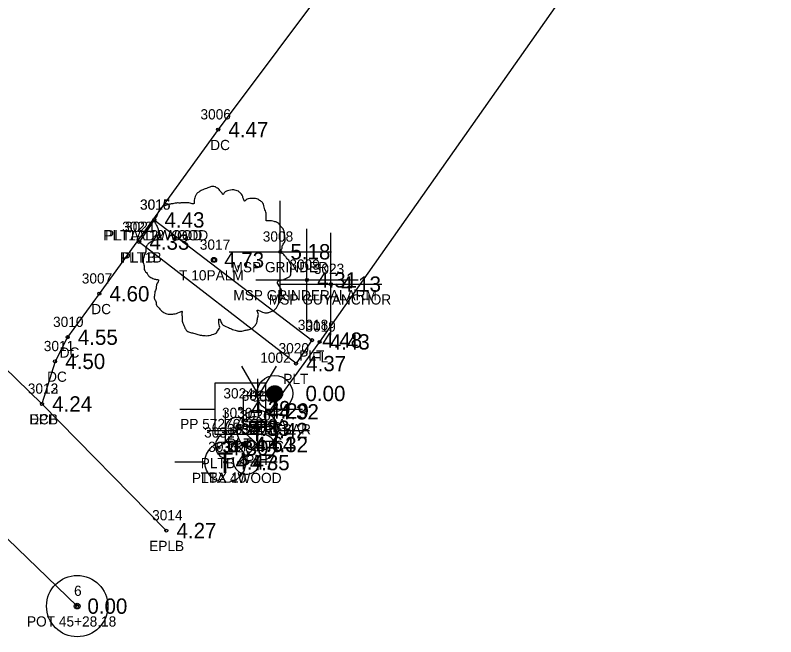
# Model space of a CAD drawing. Extents: x 2608598 to 2610682, y 641451 to 643526.
# Drawn here: x 2610257.6 to 2610332, y 641972.9 to 642033.7 of the extents above; entities that cross this region are included whole.
import ezdxf

# ---------------------------------------------------------------- set-up
doc = ezdxf.new("R2010")
doc.units = 0
for name, color, linetype in [('RD_EX_BldgApp', 7, 'Continuous'), ('RD_EX_BldgApp_txCode', 7, 'Continuous'), ('RD_EX_Conc', 7, 'Continuous'), ('RD_EX_Conc_txCode', 7, 'Continuous'), ('RD_EX_DV_Prop_txCode', 7, 'Continuous'), ('RD_EX_DV_PropPin', 7, 'Continuous'), ('RD_EX_Fence_Other', 7, 'Continuous'), ('RD_EX_Fence_Other_txCode', 7, 'Continuous'), ('RD_EX_Misc', 7, 'Continuous'), ('RD_EX_Misc_txCode', 7, 'Continuous'), ('RD_EX_Road', 7, 'Continuous'), ('RD_EX_Road_txCode', 7, 'Continuous'), ('RD_EX_TX_BldgApp_ELEV', 7, 'Continuous'), ('RD_EX_TX_Conc_ELEV', 7, 'Continuous'), ('RD_EX_TX_DV_Prop_ELEV', 7, 'Continuous'), ('RD_EX_TX_Fence_Other_ELEV', 7, 'Continuous'), ('RD_EX_TX_Misc_ELEV', 7, 'Continuous'), ('RD_EX_TX_Road_ELEV', 7, 'Continuous'), ('RD_EX_TX_UT_ELEV', 7, 'Continuous'), ('RD_EX_TX_VEG_ELEV', 7, 'Continuous'), ('RD_EX_UT', 7, 'Continuous'), ('RD_EX_UT_txCode', 7, 'Continuous'), ('RD_EX_VEG', 7, 'Continuous'), ('RD_EX_VEG_txCode', 7, 'Continuous'), ('RD_HC_Cl', 7, 'Continuous'), ('RD_HC_Data', 7, 'Continuous'), ('RD_HC_Survey_ELEV', 7, 'Continuous'), ('RD_HC_txCode', 7, 'Continuous'), ('RD_SMD_Locator', 7, 'Continuous')]:
    doc.layers.add(name, color=color, linetype=linetype)

msp = doc.modelspace()

# ---------------------------------------------------------------- linework, layer by layer
at = {"layer": 'RD_EX_BldgApp'}
msp.add_line((2610271.215, 642013.631), (2610269.738, 642011.463), dxfattribs=at)
for points in [[(2610271.215, 642013.631), (2610286.635, 642001.871), (2610285.075, 641999.583), (2610269.738, 642011.463)], [(2610279.547, 641989.897), (2610281.347, 641991.666), (2610279.543, 641993.257), (2610277.471, 641991.345)]]:
    msp.add_lwpolyline(points, dxfattribs=at)
at = {"layer": 'RD_EX_Conc'}
msp.add_lwpolyline([(2610289.126, 642038.103), (2610277.463, 642022.461), (2610265.831, 642006.412), (2610262.737, 642002.162), (2610261.507, 641999.797), (2610260.227, 641995.633)], dxfattribs=at)
at = {"layer": 'RD_EX_DV_PropPin'}
for p, q in [((2610282.336, 641996.287), (2610282.336, 641997.026)), ((2610282.371, 641996.23), (2610282.371, 641997.083)), ((2610282.406, 641996.183), (2610282.406, 641997.131)), ((2610282.441, 641996.142), (2610282.441, 641997.172)), ((2610282.476, 641996.106), (2610282.476, 641997.207)), ((2610282.511, 641996.075), (2610282.511, 641997.239)), ((2610282.546, 641996.047), (2610282.546, 641997.267)), ((2610282.582, 641996.022), (2610282.582, 641997.291)), ((2610282.617, 641996), (2610282.617, 641997.313)), ((2610282.652, 641995.981), (2610282.652, 641997.332)), ((2610282.687, 641995.964), (2610282.687, 641997.349)), ((2610282.722, 641995.949), (2610282.722, 641997.364)), ((2610282.757, 641995.936), (2610282.757, 641997.377)), ((2610282.792, 641995.925), (2610282.792, 641997.388)), ((2610282.827, 641995.916), (2610282.827, 641997.397)), ((2610282.862, 641995.909), (2610282.862, 641997.405)), ((2610282.897, 641995.903), (2610282.897, 641997.41)), ((2610282.932, 641995.899), (2610282.932, 641997.414)), ((2610282.967, 641995.896), (2610282.967, 641997.417)), ((2610283.002, 641995.896), (2610283.002, 641997.418)), ((2610283.037, 641995.896), (2610283.037, 641997.417)), ((2610283.072, 641995.899), (2610283.072, 641997.414)), ((2610283.107, 641995.903), (2610283.107, 641997.41)), ((2610283.142, 641995.909), (2610283.142, 641997.405)), ((2610283.177, 641995.916), (2610283.177, 641997.397)), ((2610283.212, 641995.925), (2610283.212, 641997.388)), ((2610283.247, 641995.936), (2610283.247, 641997.377)), ((2610283.282, 641995.949), (2610283.282, 641997.364)), ((2610283.317, 641995.964), (2610283.317, 641997.349)), ((2610283.352, 641995.981), (2610283.352, 641997.332)), ((2610283.387, 641996), (2610283.387, 641997.313)), ((2610283.422, 641996.022), (2610283.422, 641997.291)), ((2610283.457, 641996.047), (2610283.457, 641997.267)), ((2610283.492, 641996.075), (2610283.492, 641997.239)), ((2610283.527, 641996.106), (2610283.527, 641997.207)), ((2610283.562, 641996.142), (2610283.562, 641997.172)), ((2610283.597, 641996.183), (2610283.597, 641997.131)), ((2610283.632, 641996.23), (2610283.632, 641997.083)), ((2610283.667, 641996.287), (2610283.667, 641997.026)), ((2610282.266, 641996.461), (2610282.266, 641996.853)), ((2610282.301, 641996.359), (2610282.301, 641996.955)), ((2610283.702, 641996.359), (2610283.702, 641996.955)), ((2610283.737, 641996.461), (2610283.737, 641996.853))]:
    msp.add_line(p, q, dxfattribs=at)
for radius in [1.75, 0.761]:
    msp.add_circle((2610283.002, 641996.657), radius, dxfattribs=at)
at = {"layer": 'RD_EX_Fence_Other'}
msp.add_lwpolyline([(2610332.001, 642065.152), (2610287.379, 642001.703), (2610282.404, 641994.867)], dxfattribs=at)
at = {"layer": 'RD_EX_Misc'}
for p, q in [((2610283.532, 642005.515), (2610283.532, 642015.515)), ((2610286.138, 642002.763), (2610286.138, 642012.763)), ((2610288.482, 642002.354), (2610288.482, 642012.354)), ((2610278.532, 642010.515), (2610288.532, 642010.515)), ((2610281.138, 642007.763), (2610291.138, 642007.763)), ((2610283.482, 642007.354), (2610293.482, 642007.354))]:
    msp.add_line(p, q, dxfattribs=at)
at = {"layer": 'RD_EX_Road'}
msp.add_lwpolyline([(2609576.606, 642656.063), (2609590.876, 642642.238), (2609605.189, 642628.776), (2609627.581, 642607.088), (2609646.03, 642589.107), (2609702.182, 642534.044), (2609780.351, 642458.947), (2609858.794, 642382.828), (2609938.323, 642306.422), (2610008.617, 642239.319), (2610086.297, 642162.544), (2610164.179, 642089.488), (2610189.201, 642065.464), (2610214.781, 642040.191), (2610225.859, 642030.159), (2610226.316, 642028.389), (2610235.43, 642019.753), (2610260.227, 641995.633), (2610272.389, 641983.247)], dxfattribs=at)
at = {"layer": 'RD_EX_UT'}
for p, q in [((2610281.427, 641996.443), (2610279.76, 641999.329)), ((2610281.427, 641996.443), (2610283.167, 641999.329)), ((2610281.311, 641998.099), (2610281.311, 641995.03)), ((2610282.13, 641997.681), (2610277.13, 641997.681)), ((2610277.13, 641997.681), (2610277.13, 641992.681)), ((2610282.13, 641992.681), (2610282.13, 641997.681)), ((2610273.699, 641995.119), (2610277.168, 641995.119)), ((2610278.158, 641995.01), (2610278.158, 641991.94)), ((2610282.058, 641995.119), (2610285.699, 641995.119)), ((2610276.381, 641993.045), (2610279.311, 641993.045)), ((2610277.13, 641992.681), (2610282.13, 641992.681)), ((2610283.311, 641993.045), (2610286.381, 641993.045)), ((2610273.227, 641989.955), (2610276.158, 641989.955)), ((2610280.157, 641989.955), (2610283.227, 641989.955))]:
    msp.add_line(p, q, dxfattribs=at)
msp.add_lwpolyline([(2610279.927, 641993.443), (2610279.927, 641996.443), (2610282.927, 641996.443), (2610282.927, 641993.443)], close=True, dxfattribs=at)
for centre in [(2610281.311, 641993.03), (2610278.158, 641989.94)]:
    msp.add_circle(centre, 2, dxfattribs=at)
at = {"layer": 'RD_EX_VEG'}
for centre, radius in [((2610277.052, 642009.716), 0.25), ((2610277.039, 642009.697), 0.0001), ((2610280, 641991.68), 0.25)]:
    msp.add_circle(centre, radius, dxfattribs=at)
for centre, radius, start, end in [((2610279.279, 641993.227), 1.084, 34.97629, 204.75602), ((2610281.046, 641993.382), 0.995, 308.76261, 152.04674), ((2610278.437, 641991.524), 1.257, 96.45179, 294.73401), ((2610281.84, 641991.4), 1.218, 256.56668, 98.10463), ((2610280.246, 641990.083), 1.318, 166.88266, 5.75893)]:
    msp.add_arc(centre, radius, start, end, dxfattribs=at)
for points in [[(2610277.184, 642016.884), (2610276.884, 642016.909), (2610276.559, 642016.809), (2610276.309, 642016.709), (2610276.084, 642016.634), (2610275.859, 642016.534), (2610275.56, 642016.359), (2610275.335, 642016.159), (2610275.21, 642015.909), (2610275.16, 642015.684), (2610275.11, 642015.409), (2610275.11, 642015.234), (2610274.985, 642015.209), (2610274.835, 642015.234), (2610274.585, 642015.309), (2610274.335, 642015.309), (2610274.085, 642015.309), (2610273.735, 642015.284), (2610273.385, 642015.284), (2610273.111, 642015.234), (2610272.786, 642015.184), (2610272.411, 642015.059), (2610272.061, 642014.934), (2610271.761, 642014.684), (2610271.511, 642014.21), (2610271.386, 642013.86), (2610271.236, 642013.61), (2610271.386, 642013.16), (2610271.561, 642012.81), (2610271.586, 642012.61), (2610271.661, 642012.186), (2610271.761, 642011.961), (2610271.886, 642011.761), (2610271.811, 642011.736), (2610271.436, 642011.686), (2610271.136, 642011.586), (2610270.712, 642011.361), (2610270.487, 642011.136), (2610270.387, 642010.811), (2610270.362, 642010.461), (2610270.262, 642010.261), (2610270.187, 642009.987), (2610270.162, 642009.912), (2610270.112, 642009.587), (2610270.212, 642009.137), (2610270.237, 642008.787), (2610270.362, 642008.562), (2610270.512, 642008.387), (2610270.687, 642008.137), (2610271.086, 642007.912), (2610271.411, 642007.812), (2610271.611, 642007.788), (2610271.436, 642007.288), (2610271.386, 642006.938), (2610271.261, 642006.538), (2610271.261, 642006.463), (2610271.211, 642005.988), (2610271.361, 642005.663), (2610271.436, 642005.289), (2610271.611, 642005.064), (2610271.886, 642004.764), (2610272.211, 642004.539), (2610272.711, 642004.414), (2610273.111, 642004.439), (2610273.685, 642004.614), (2610273.935, 642004.689), (2610273.91, 642004.514), (2610273.935, 642004.139), (2610273.935, 642003.714), (2610274.085, 642003.389), (2610274.185, 642003.115), (2610274.335, 642002.865), (2610274.66, 642002.64), (2610275.06, 642002.565), (2610275.485, 642002.415), (2610275.934, 642002.34), (2610276.434, 642002.315), (2610277.034, 642002.465), (2610277.309, 642002.59), (2610277.409, 642002.765), (2610277.609, 642003.14), (2610277.559, 642003.364), (2610277.584, 642003.964), (2610277.684, 642003.789), (2610277.859, 642003.439), (2610278.358, 642003.14), (2610278.758, 642002.965), (2610279.233, 642002.815), (2610279.533, 642002.74), (2610280.008, 642002.815), (2610280.382, 642002.89), (2610280.757, 642003.015), (2610281.057, 642003.289), (2610281.232, 642003.564), (2610281.282, 642003.839), (2610281.357, 642004.214), (2610281.407, 642004.389)], [(2610281.407, 642004.389), (2610281.332, 642004.564), (2610281.282, 642004.814), (2610281.357, 642004.789), (2610281.532, 642004.739), (2610281.807, 642004.614), (2610282.032, 642004.539), (2610282.357, 642004.564), (2610282.631, 642004.664), (2610283.081, 642004.939), (2610283.356, 642005.414), (2610283.631, 642005.813), (2610283.706, 642006.138), (2610283.656, 642006.363), (2610283.631, 642006.863), (2610283.431, 642007.113), (2610283.381, 642007.238), (2610283.281, 642007.638), (2610283.356, 642007.688), (2610283.631, 642007.738), (2610284.006, 642007.862), (2610284.281, 642007.987), (2610284.506, 642008.162), (2610284.581, 642008.387), (2610284.556, 642008.787), (2610284.606, 642009.187), (2610284.531, 642009.337), (2610284.431, 642009.487), (2610284.356, 642009.687), (2610284.206, 642009.837), (2610284.106, 642009.987), (2610284.006, 642010.086), (2610283.881, 642010.236), (2610283.706, 642010.361), (2610283.556, 642010.411), (2610283.506, 642010.561), (2610283.656, 642010.761), (2610283.706, 642010.861), (2610283.731, 642011.086), (2610283.956, 642011.436), (2610284.006, 642011.836), (2610283.956, 642012.261), (2610283.906, 642012.535), (2610283.756, 642012.81), (2610283.556, 642013.06), (2610283.431, 642013.235), (2610283.256, 642013.36), (2610282.931, 642013.485), (2610282.681, 642013.535), (2610282.332, 642013.535), (2610282.132, 642013.585), (2610282.157, 642013.635), (2610282.157, 642013.785), (2610282.157, 642014.06), (2610282.082, 642014.51), (2610281.932, 642015.009), (2610281.932, 642015.034), (2610281.832, 642015.284), (2610281.607, 642015.484), (2610281.432, 642015.584), (2610281.232, 642015.709), (2610280.982, 642015.734), (2610280.682, 642015.734), (2610280.407, 642015.684), (2610280.207, 642015.584), (2610280.033, 642015.459), (2610279.958, 642015.609), (2610279.858, 642015.909), (2610279.808, 642016.059), (2610279.658, 642016.234), (2610279.433, 642016.434), (2610278.983, 642016.559), (2610278.358, 642016.484), (2610278.058, 642016.284), (2610277.908, 642016.109), (2610277.859, 642016.234), (2610277.659, 642016.434), (2610277.559, 642016.609), (2610277.384, 642016.734), (2610277.234, 642016.834), (2610277.134, 642016.884)]]:
    msp.add_spline(points, degree=3, dxfattribs=at)
at = {"layer": 'RD_HC_Cl'}
msp.add_line((2610092.394, 642140.787), (2610263.672, 641975.859), dxfattribs=at)
at = {"layer": 'RD_HC_Data'}
for radius in [3, 0.282]:
    msp.add_circle((2610263.672, 641975.859), radius, dxfattribs=at)
at = {"layer": 'RD_SMD_Locator'}
for centre in [(2610277.463, 642022.461), (2610271.215, 642013.631), (2610271.215, 642013.631), (2610269.738, 642011.463), (2610269.738, 642011.463), (2610283.532, 642010.515), (2610277.052, 642009.716), (2610286.138, 642007.763), (2610288.482, 642007.354), (2610265.831, 642006.412), (2610262.737, 642002.162), (2610286.635, 642001.871), (2610287.379, 642001.703), (2610261.507, 641999.797), (2610285.075, 641999.583), (2610283.002, 641996.657), (2610260.227, 641995.633), (2610260.227, 641995.633), (2610279.639, 641995.172), (2610281.427, 641994.943), (2610282.404, 641994.867), (2610279.543, 641993.257), (2610281.311, 641993.03), (2610280, 641991.68), (2610281.347, 641991.666), (2610277.471, 641991.345), (2610278.158, 641989.94), (2610279.547, 641989.897), (2610272.389, 641983.247), (2610263.672, 641975.859)]:
    msp.add_circle(centre, 0.15, dxfattribs=at)

# ---------------------------------------------------------------- texts
at = {"layer": 'RD_EX_BldgApp_txCode'}
for s, p in [('3016', (2610269.805, 642014.631)), ('3015', (2610269.829, 642014.631)), ('3022', (2610268.068, 642012.463)), ('3021', (2610268.352, 642012.463)), ('PLT1A 12WOOD', (2610266.23, 642011.631)), ('PLTA 12WOOD', (2610266.396, 642011.631)), ('PLT1B', (2610267.856, 642009.463)), ('PLTB', (2610268.021, 642009.463)), ('3018', (2610285.249, 642002.871)), ('3020', (2610283.367, 642000.583)), ('PLT', (2610285.391, 641999.871)), ('PLT', (2610283.831, 641997.583)), ('3030', (2610277.834, 641994.257)), ('3031', (2610276.086, 641992.345)), ('3029', (2610279.678, 641992.666)), ('3028', (2610277.878, 641990.897)), ('PLT', (2610278.299, 641991.257)), ('PLTB', (2610275.755, 641989.345)), ('PLT', (2610280.103, 641989.666)), ('PLTA 4WOOD', (2610274.893, 641987.897))]:
    msp.add_text(s, height=1, dxfattribs=at).set_placement(p)
at = {"layer": 'RD_EX_Conc_txCode'}
for s, p in [('3006', (2610275.73, 642023.461)), ('DC', (2610276.683, 642020.461)), ('3007', (2610264.122, 642007.412)), ('DC', (2610265.051, 642004.412)), ('3010', (2610261.311, 642003.162)), ('3011', (2610260.405, 642000.797)), ('DC', (2610261.957, 642000.162)), ('DC', (2610260.728, 641997.797)), ('3012', (2610258.841, 641996.633)), ('DCB', (2610258.975, 641993.633))]:
    msp.add_text(s, height=1, dxfattribs=at).set_placement(p)
at = {"layer": 'RD_EX_DV_Prop_txCode'}
for s, p in [('1002', (2610281.577, 641999.657)), ('IP #4REBAR', (2610278.805, 641992.657))]:
    msp.add_text(s, height=1, dxfattribs=at).set_placement(p)
at = {"layer": 'RD_EX_Fence_Other_txCode'}
for s, p in [('3019', (2610285.993, 642002.703)), ('FL', (2610286.647, 641999.703)), ('3027', (2610280.735, 641995.867)), ('FLB', (2610281.199, 641992.867))]:
    msp.add_text(s, height=1, dxfattribs=at).set_placement(p)
at = {"layer": 'RD_EX_Misc_txCode'}
for s, p in [('3008', (2610281.824, 642011.515)), ('3009', (2610284.429, 642008.763)), ('MSP GRINDER', (2610278.769, 642008.515)), ('3023', (2610286.813, 642008.354)), ('MSP GRINDERALARM', (2610278.941, 642005.763)), ('MSP GUYANCHOR', (2610282.419, 642005.354))]:
    msp.add_text(s, height=1, dxfattribs=at).set_placement(p)
at = {"layer": 'RD_EX_Road_txCode'}
for s, p in [('3013', (2610258.841, 641996.633)), ('EPL', (2610259.023, 641993.633)), ('3014', (2610271.003, 641984.247)), ('EPLB', (2610270.711, 641981.247))]:
    msp.add_text(s, height=1, dxfattribs=at).set_placement(p)
at = {"layer": 'RD_EX_TX_BldgApp_ELEV'}
for s, p in [('4.43', (2610272.215, 642012.881)), ('4.43', (2610272.215, 642012.881)), ('4.33', (2610270.738, 642010.713)), ('4.33', (2610270.738, 642010.713)), ('4.48', (2610287.635, 642001.121)), ('4.37', (2610286.075, 641998.833)), ('4.33', (2610280.543, 641992.507)), ('4.30', (2610278.471, 641990.595)), ('4.32', (2610282.347, 641990.916)), ('4.35', (2610280.547, 641989.147))]:
    msp.add_text(s, height=1.5, dxfattribs=at).set_placement(p)
at = {"layer": 'RD_EX_TX_Conc_ELEV'}
for s, p in [('4.47', (2610278.463, 642021.711)), ('4.60', (2610266.831, 642005.662)), ('4.55', (2610263.737, 642001.412)), ('4.50', (2610262.507, 641999.047)), ('4.24', (2610261.227, 641994.883))]:
    msp.add_text(s, height=1.5, dxfattribs=at).set_placement(p)
at = {"layer": 'RD_EX_TX_DV_Prop_ELEV'}
msp.add_text('0.00', height=1.5, dxfattribs=at).set_placement((2610286.002, 641995.907))
at = {"layer": 'RD_EX_TX_Fence_Other_ELEV'}
for s, p in [('4.43', (2610288.379, 642000.953)), ('4.32', (2610283.404, 641994.117))]:
    msp.add_text(s, height=1.5, dxfattribs=at).set_placement(p)
at = {"layer": 'RD_EX_TX_Misc_ELEV'}
for s, p in [('5.18', (2610284.532, 642009.765)), ('4.31', (2610287.138, 642007.013)), ('4.13', (2610289.482, 642006.604))]:
    msp.add_text(s, height=1.5, dxfattribs=at).set_placement(p)
at = {"layer": 'RD_EX_TX_Road_ELEV'}
for s, p in [('4.24', (2610261.227, 641994.883)), ('4.27', (2610273.389, 641982.497))]:
    msp.add_text(s, height=1.5, dxfattribs=at).set_placement(p)
at = {"layer": 'RD_EX_TX_UT_ELEV'}
for s, p in [('4.29', (2610282.427, 641994.193)), ('4.42', (2610282.311, 641992.28)), ('4.47', (2610279.158, 641989.19))]:
    msp.add_text(s, height=1.5, dxfattribs=at).set_placement(p)
at = {"layer": 'RD_EX_TX_VEG_ELEV'}
for s, p in [('4.73', (2610278.052, 642008.966)), ('4.64', (2610281, 641990.93))]:
    msp.add_text(s, height=1.5, dxfattribs=at).set_placement(p)
at = {"layer": 'RD_EX_UT'}
for p in [(2610280.462, 641991.982), (2610277.308, 641988.893)]:
    msp.add_text('T', height=2, dxfattribs=at).set_placement(p)
at = {"layer": 'RD_EX_UT_txCode'}
for s, p in [('3024', (2610277.969, 641996.172)), ('3025', (2610279.757, 641995.943)), ('3026', (2610279.618, 641994.03)), ('PP 57276SCPSA', (2610273.741, 641993.172)), ('TVP', (2610280.143, 641992.943)), ('3033', (2610276.488, 641990.94)), ('TPP HTC', (2610278.162, 641991.03)), ('TBX 10', (2610275.748, 641987.94))]:
    msp.add_text(s, height=1, dxfattribs=at).set_placement(p)
at = {"layer": 'RD_EX_VEG_txCode'}
for s, p in [('3017', (2610275.666, 642010.716)), ('T 10PALM', (2610273.642, 642007.716)), ('3032', (2610278.331, 641992.68)), ('S', (2610279.693, 641989.68))]:
    msp.add_text(s, height=1, dxfattribs=at).set_placement(p)
at = {"layer": 'RD_HC_Survey_ELEV'}
for s, p in [('4.29', (2610280.639, 641994.422)), ('0.00', (2610264.672, 641975.109))]:
    msp.add_text(s, height=1.5, dxfattribs=at).set_placement(p)
at = {"layer": 'RD_HC_txCode'}
for s, p in [('6', (2610263.365, 641976.859)), ('POT 45+28.18', (2610258.758, 641973.859))]:
    msp.add_text(s, height=1, dxfattribs=at).set_placement(p)

doc.saveas('drawing.dxf')
